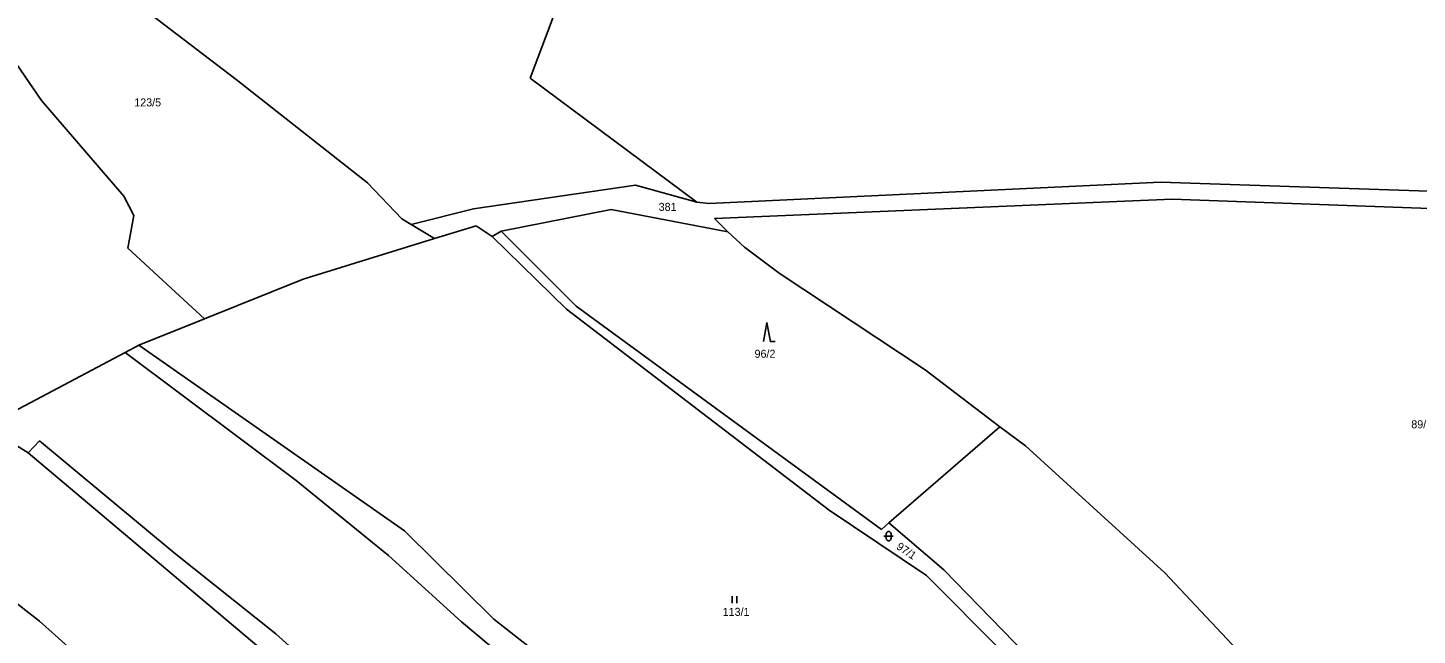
# Model space of a CAD drawing. Extents: x -811039 to -805820, y -1161436 to -1155864.
# Drawn here: x -807066.9 to -806771.7, y -1158195.9 to -1158066.9 of the extents above; entities that cross this region are included whole.
import ezdxf

# ---------------------------------------------------------------- set-up
doc = ezdxf.new("R2010")
doc.units = 0
for name, color, linetype in [('Default', 7, 'Continuous'), ('Hranice parcel', 7, 'Continuous'), ('Parcelní čísla', 7, 'Continuous'), ('Značky kultur', 7, 'Continuous')]:
    doc.layers.add(name, color=color, linetype=linetype)

# ---------------------------------------------------------------- blocks, each defined once
blk = doc.blocks.new('306')
at = {"layer": 'Default'}
for p, q in [((-0.5, 1.5), (-0.5, 0)), ((0.5, 0), (0.5, 1.5))]:
    blk.add_line(p, q, dxfattribs=at)
blk = doc.blocks.new('308')
at = {"layer": 'Default'}
blk.add_lwpolyline([(-0.75, 0), (0, 4), (0.75, 0), (1.75, 0)], dxfattribs=at)
blk = doc.blocks.new('316')
at = {"layer": 'Default'}
for points in [[(-1, 1), (0.27, 1), (1, 1)], [(-0.5, 1.5), (-0.4, 1.79), (-0.15, 1.97), (0.16, 1.97), (0.41, 1.79), (0.51, 1.5), (0.51, 0.5), (0.41, 0.21), (0.16, 0.03), (-0.15, 0.03), (-0.4, 0.21), (-0.5, 0.5), (-0.5, 1.5)]]:
    blk.add_lwpolyline(points, dxfattribs=at)

msp = doc.modelspace()

# ---------------------------------------------------------------- linework, layer by layer
at = {"layer": 'Hranice parcel'}
for p, q in [((-806960.13, -1158077.6), (-806950.1, -1158050.97)), ((-807022.58, -1158077.9), (-807044.99, -1158060.79)), ((-807063.97, -1158082.38), (-807071.97, -1158070.67)), ((-806994.74, -1158099.86), (-807022.58, -1158077.9)), ((-806960.13, -1158077.6), (-806924.76, -1158103.98)), ((-807046.51, -1158102.69), (-807063.97, -1158082.38)), ((-806987.44, -1158107.47), (-806994.74, -1158099.86)), ((-806972.21, -1158105.33), (-806937.74, -1158100.34)), ((-806937.74, -1158100.34), (-806924.76, -1158103.98)), ((-806922.15, -1158104.21), (-806826.2, -1158099.73)), ((-806755.75, -1158102.03), (-806826.2, -1158099.73)), ((-807044.32, -1158106.75), (-807046.51, -1158102.69)), ((-806823.76, -1158103.31), (-806921.01, -1158107.38)), ((-806754.99, -1158105.78), (-806823.76, -1158103.31)), ((-806985.4, -1158108.7), (-806972.21, -1158105.33)), ((-806966.3, -1158110.08), (-806942.91, -1158105.49)), ((-806942.91, -1158105.49), (-806918.14, -1158110.23)), ((-806924.76, -1158103.98), (-806922.15, -1158104.21)), ((-807045.63, -1158113.72), (-807044.32, -1158106.75)), ((-806985.4, -1158108.7), (-806987.44, -1158107.47)), ((-806985.4, -1158108.7), (-806980.48, -1158111.68)), ((-806980.48, -1158111.68), (-806971.65, -1158108.95)), ((-806968.24, -1158111.24), (-806971.65, -1158108.95)), ((-806918.14, -1158110.23), (-806921.01, -1158107.38)), ((-806980.48, -1158111.68), (-807008.39, -1158120.31)), ((-806968.24, -1158111.24), (-806966.3, -1158110.08)), ((-806952.42, -1158126.65), (-806968.24, -1158111.24)), ((-806966.3, -1158110.08), (-806950.37, -1158126.05)), ((-806914.62, -1158113.48), (-806918.14, -1158110.23)), ((-807033.74, -1158124.65), (-807045.63, -1158113.72)), ((-806907.27, -1158119.01), (-806914.62, -1158113.48)), ((-807029.32, -1158128.7), (-807008.39, -1158120.31)), ((-806876.2, -1158139.53), (-806907.27, -1158119.01)), ((-807033.74, -1158124.65), (-807029.32, -1158128.7)), ((-806896.6, -1158169.34), (-806952.42, -1158126.65)), ((-806885.53, -1158173.39), (-806950.37, -1158126.05)), ((-807029.32, -1158128.7), (-807043.26, -1158134.29)), ((-807075.81, -1158151.48), (-807046.19, -1158135.84)), ((-807046.19, -1158135.84), (-807043.26, -1158134.29)), ((-807046.19, -1158135.84), (-807009.85, -1158162.99)), ((-806986.84, -1158173.73), (-807043.26, -1158134.29)), ((-806860.39, -1158151.65), (-806876.2, -1158139.53)), ((-807075.81, -1158151.48), (-807066.83, -1158157.18)), ((-806860.39, -1158151.65), (-806883.96, -1158172.03)), ((-806854.9, -1158155.63), (-806860.39, -1158151.65)), ((-807066.83, -1158157.18), (-807064.41, -1158154.57)), ((-807064.41, -1158154.57), (-807035.81, -1158178.4)), ((-806825.32, -1158182.62), (-806854.9, -1158155.63)), ((-807018.22, -1158198.03), (-807066.83, -1158157.18)), ((-807009.85, -1158162.99), (-806990.24, -1158178.96)), ((-806875.95, -1158183.18), (-806896.6, -1158169.34)), ((-807064.42, -1158192.88), (-807090.13, -1158172.9)), ((-806986.84, -1158173.73), (-806967.86, -1158192.42)), ((-806883.96, -1158172.03), (-806885.53, -1158173.39)), ((-806872.23, -1158182), (-806883.96, -1158172.03)), ((-807035.81, -1158178.4), (-807014.17, -1158195.54)), ((-806974.74, -1158193.03), (-806990.24, -1158178.96)), ((-806838.09, -1158217.06), (-806872.23, -1158182)), ((-806794.32, -1158215.46), (-806825.32, -1158182.62)), ((-806859.82, -1158199.37), (-806875.95, -1158183.18)), ((-807036.77, -1158217.51), (-807064.42, -1158192.88)), ((-806954.76, -1158209.69), (-806974.74, -1158193.03)), ((-806967.86, -1158192.42), (-806940.68, -1158213.7)), ((-807014.17, -1158195.54), (-806992.99, -1158214.58))]:
    msp.add_line(p, q, dxfattribs=at)

# ---------------------------------------------------------------- block references
at = {"layer": 'Značky kultur'}
for name, p in [('308', (-806909.85, -1158133.53)), ('316', (-806883.99, -1158175.85)), ('306', (-806916.76, -1158189.05))]:
    msp.add_blockref(name, p, dxfattribs=at)

# ---------------------------------------------------------------- texts
at = {"layer": 'Parcelní čísla'}
for s, p in [('123/5', (-807044.25, -1158083.62)), ('381', (-806932.84, -1158105.79)), ('96/2', (-806912.47, -1158136.97)), ('89/1', (-806772.94, -1158151.94)), ('113/1', (-806919.24, -1158191.75))]:
    msp.add_text(s, height=1.7, dxfattribs=at).set_placement(p)
msp.add_text('97/1', height=1.7, rotation=325.898, dxfattribs=at).set_placement((-806882.5, -1158177.42))

doc.saveas('drawing.dxf')
